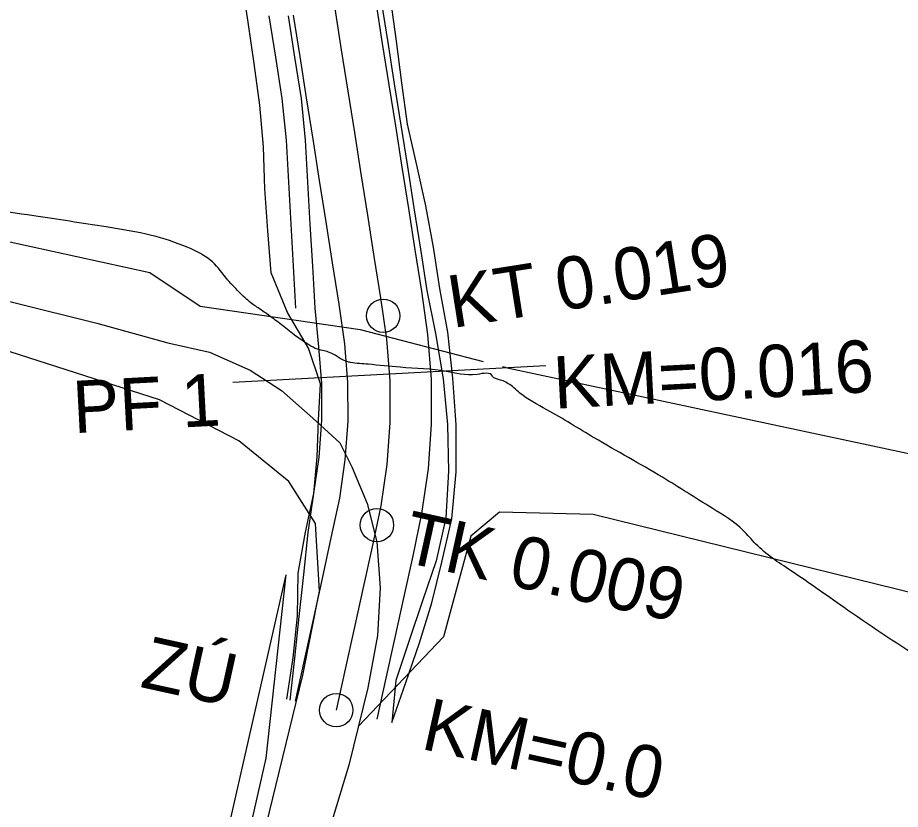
# Model space of a CAD drawing. Extents: x -477701 to -476785, y -1116511 to -1115314.
# Drawn here: x -477025.91 to -476983.69, y -1116139.76 to -1116101.91 of the extents above; entities that cross this region are included whole.
import ezdxf

# ---------------------------------------------------------------- set-up
doc = ezdxf.new("R2010")
doc.units = 0
for name, color, linetype in [('1', 7, 'Continuous'), ('BYBLOCK', 7, 'Continuous'), ('hrana_P', 7, 'Continuous'), ('hrana_R', 7, 'Continuous'), ('POLYGONY_SITUACE_PF', 7, 'Continuous'), ('POLYGONY_SITUACE_PF_POPISY', 7, 'Continuous'), ('POLYGONY_SITUACE_PO', 7, 'Continuous'), ('SVK_STAT', 7, 'Continuous'), ('Vrstevnice_vedlejsi', 7, 'Continuous')]:
    doc.layers.add(name, color=color, linetype=linetype)

msp = doc.modelspace()

# ---------------------------------------------------------------- linework, layer by layer
at = {"layer": 'hrana_P'}
for points in [[(-477014.887, -1116102.126), (-477015.192, -1116100.149)], [(-477007.787, -1116103.031), (-477008.062, -1116101.05)], [(-477014.604, -1116104.106), (-477014.887, -1116102.126)], [(-477007.537, -1116105.017), (-477007.787, -1116103.031)], [(-477014.322, -1116106.086), (-477014.604, -1116104.106)], [(-477007.261, -1116106.998), (-477007.537, -1116105.017)], [(-477014.156, -1116108.085), (-477014.322, -1116106.086)], [(-477006.82, -1116108.953), (-477007.261, -1116106.998)], [(-477014.082, -1116110.098), (-477014.156, -1116108.085)], [(-477006.379, -1116110.908), (-477006.82, -1116108.953)], [(-477013.95, -1116112.102), (-477014.082, -1116110.098)], [(-477006.014, -1116112.875), (-477006.379, -1116110.908)], [(-477013.79, -1116114.101), (-477013.95, -1116112.102)], [(-477005.719, -1116114.854), (-477006.014, -1116112.875)], [(-477013.008, -1116116.003), (-477013.79, -1116114.101)], [(-477005.329, -1116116.942), (-477005.719, -1116114.854)], [(-477011.99, -1116117.708), (-477013.008, -1116116.003)], [(-477005.093, -1116119.151), (-477005.329, -1116116.942)], [(-477011.425, -1116119.408), (-477011.99, -1116117.708)], [(-477011.517, -1116121.159), (-477011.425, -1116119.408)], [(-477004.934, -1116121.38), (-477005.093, -1116119.151)], [(-477011.579, -1116122.908), (-477011.517, -1116121.159)], [(-477004.931, -1116123.627), (-477004.934, -1116121.38)], [(-477011.742, -1116124.658), (-477011.579, -1116122.908)], [(-477005.138, -1116125.872), (-477004.931, -1116123.627)], [(-477012.135, -1116126.503), (-477011.742, -1116124.658)], [(-477005.617, -1116127.937), (-477005.138, -1116125.872)], [(-477012.49, -1116128.473), (-477012.135, -1116126.503)], [(-477006.107, -1116129.877), (-477005.617, -1116127.937)], [(-477012.52, -1116130.514), (-477012.49, -1116128.473)], [(-477006.689, -1116131.797), (-477006.107, -1116129.877)], [(-477012.728, -1116132.516), (-477012.52, -1116130.514)], [(-477007.346, -1116133.7), (-477006.689, -1116131.797)], [(-477013.038, -1116134.495), (-477012.728, -1116132.516)], [(-477008.009, -1116135.602), (-477007.346, -1116133.7)]]:
    msp.add_lwpolyline(points, dxfattribs=at)
at = {"layer": 'hrana_R'}
for points in [[(-477008.452, -1116103.136), (-477008.764, -1116101.161)], [(-477008.517, -1116101.122), (-477008.205, -1116103.097)], [(-477010.739, -1116101.472), (-477010.428, -1116103.448)], [(-477013.568, -1116103.798), (-477013.88, -1116101.823)], [(-477012.65, -1116103.798), (-477012.962, -1116101.823)], [(-477012.403, -1116103.759), (-477012.715, -1116101.784)], [(-477008.141, -1116105.112), (-477008.452, -1116103.136)], [(-477008.205, -1116103.097), (-477007.894, -1116105.073)], [(-477013.257, -1116105.774), (-477013.568, -1116103.798)], [(-477012.339, -1116105.774), (-477012.65, -1116103.798)], [(-477012.092, -1116105.735), (-477012.403, -1116103.759)], [(-477010.428, -1116103.448), (-477010.116, -1116105.423)], [(-477007.829, -1116107.087), (-477008.141, -1116105.112)], [(-477007.894, -1116105.073), (-477007.582, -1116107.049)], [(-477010.116, -1116105.423), (-477009.805, -1116107.399)], [(-477013.057, -1116107.767), (-477013.257, -1116105.774)], [(-477012.139, -1116107.767), (-477012.339, -1116105.774)], [(-477011.781, -1116107.71), (-477012.092, -1116105.735)], [(-477007.518, -1116109.063), (-477007.829, -1116107.087)], [(-477007.582, -1116107.049), (-477007.271, -1116109.024)], [(-477009.805, -1116107.399), (-477009.493, -1116109.375)], [(-477012.943, -1116109.774), (-477013.057, -1116107.767)], [(-477012.025, -1116109.774), (-477012.139, -1116107.767)], [(-477011.469, -1116109.686), (-477011.781, -1116107.71)], [(-477007.206, -1116111.039), (-477007.518, -1116109.063)], [(-477007.271, -1116109.024), (-477006.959, -1116111)], [(-477011.158, -1116111.662), (-477011.469, -1116109.686)], [(-477009.493, -1116109.375), (-477009.182, -1116111.35)], [(-477012.829, -1116111.78), (-477012.943, -1116109.774)], [(-477011.911, -1116111.78), (-477012.025, -1116109.774)], [(-477006.959, -1116111), (-477006.648, -1116112.975)], [(-477009.182, -1116111.35), (-477008.871, -1116113.326)], [(-477006.895, -1116113.014), (-477007.206, -1116111.039)], [(-477012.715, -1116113.787), (-477012.829, -1116111.78)], [(-477011.797, -1116113.787), (-477011.911, -1116111.78)], [(-477010.846, -1116113.637), (-477011.158, -1116111.662)], [(-477006.584, -1116114.99), (-477006.895, -1116113.014)], [(-477006.648, -1116112.975), (-477006.337, -1116114.951)], [(-477008.871, -1116113.326), (-477008.559, -1116115.301)], [(-477012.601, -1116115.794), (-477012.715, -1116113.787)], [(-477011.683, -1116115.794), (-477011.797, -1116113.787)], [(-477010.535, -1116115.613), (-477010.846, -1116113.637)], [(-477006.284, -1116117.052), (-477006.584, -1116114.99)], [(-477006.337, -1116114.951), (-477005.924, -1116117.01)], [(-477010.258, -1116117.509), (-477010.535, -1116115.613)], [(-477008.559, -1116115.301), (-477008.271, -1116117.28)], [(-477012.601, -1116115.794), (-477012.601, -1116115.794)], [(-477011.5, -1116117.652), (-477011.683, -1116115.794)], [(-477008.271, -1116117.28), (-477008.116, -1116119.274)], [(-477006.118, -1116119.193), (-477006.284, -1116117.052)], [(-477005.924, -1116117.01), (-477005.558, -1116119.17)], [(-477011.364, -1116119.405), (-477011.5, -1116117.652)], [(-477010.115, -1116119.355), (-477010.258, -1116117.509)], [(-477011.358, -1116121.164), (-477011.364, -1116119.405)], [(-477010.108, -1116121.206), (-477010.115, -1116119.355)], [(-477008.116, -1116119.274), (-477008.109, -1116121.273)], [(-477006.11, -1116121.341), (-477006.118, -1116119.193)], [(-477005.558, -1116119.17), (-477005.352, -1116121.366)], [(-477011.482, -1116122.919), (-477011.358, -1116121.164)], [(-477010.239, -1116123.053), (-477010.108, -1116121.206)], [(-477008.109, -1116121.273), (-477008.25, -1116123.268)], [(-477006.262, -1116123.483), (-477006.11, -1116121.341)], [(-477005.352, -1116121.366), (-477005.31, -1116123.586)], [(-477011.735, -1116124.659), (-477011.482, -1116122.919)], [(-477010.506, -1116124.885), (-477010.239, -1116123.053)], [(-477008.25, -1116123.268), (-477008.539, -1116125.247)], [(-477006.572, -1116125.608), (-477006.262, -1116123.483)], [(-477005.31, -1116123.586), (-477005.434, -1116125.817)], [(-477012.013, -1116126.53), (-477011.735, -1116124.659)], [(-477010.906, -1116126.773), (-477010.506, -1116124.885)], [(-477008.539, -1116125.247), (-477008.953, -1116127.203)], [(-477006.999, -1116127.633), (-477006.572, -1116125.608)], [(-477005.434, -1116125.817), (-477005.893, -1116127.877)], [(-477012.227, -1116128.53), (-477012.013, -1116126.53)], [(-477011.336, -1116128.727), (-477010.906, -1116126.773)], [(-477008.953, -1116127.203), (-477009.383, -1116129.156)], [(-477007.429, -1116129.586), (-477006.999, -1116127.633)], [(-477005.893, -1116127.877), (-477006.538, -1116129.782)], [(-477012.441, -1116130.531), (-477012.227, -1116128.53)], [(-477011.766, -1116130.68), (-477011.336, -1116128.727)], [(-477009.383, -1116129.156), (-477009.812, -1116131.11)], [(-477007.859, -1116131.54), (-477007.429, -1116129.586)], [(-477006.538, -1116129.782), (-477007.184, -1116131.688)], [(-477012.655, -1116132.532), (-477012.441, -1116130.531)], [(-477012.195, -1116132.633), (-477011.766, -1116130.68)], [(-477009.812, -1116131.11), (-477010.242, -1116133.063)], [(-477008.289, -1116133.493), (-477007.859, -1116131.54)], [(-477007.184, -1116131.688), (-477007.829, -1116133.594)], [(-477012.869, -1116134.533), (-477012.655, -1116132.532)], [(-477012.625, -1116134.586), (-477012.195, -1116132.633)], [(-477010.242, -1116133.063), (-477010.672, -1116135.016)], [(-477008.719, -1116135.446), (-477008.289, -1116133.493)], [(-477007.829, -1116133.594), (-477008.009, -1116135.602)]]:
    msp.add_lwpolyline(points, dxfattribs=at)
at = {"layer": 'POLYGONY_SITUACE_PF'}
msp.add_lwpolyline([(-477015.621, -1116119.334), (-477008.132, -1116118.937), (-477000.642, -1116118.541)], dxfattribs=at)
at = {"layer": 'POLYGONY_SITUACE_PO'}
for centre in [(-477008.423, -1116116.161), (-477008.725, -1116126.169), (-477010.672, -1116135.016)]:
    msp.add_circle(centre, 0.8, dxfattribs=at)
at = {"layer": 'SVK_STAT'}
for p, q in [((-477002.861, -1116125.548), (-477004.234, -1116126.692)), ((-476998.39, -1116125.659), (-477002.861, -1116125.548)), ((-476970.394, -1116132.552), (-476998.39, -1116125.659)), ((-477004.234, -1116126.692), (-477005.543, -1116131.513)), ((-477005.543, -1116131.513), (-477009.615, -1116135.793))]:
    msp.add_line(p, q, dxfattribs=at)
for points in [[(-477082.723, -1116100.585), (-477053.348, -1116106.692), (-477019.581, -1116114.084), (-477017.176, -1116115.701), (-477009.531, -1116116.815), (-477003.649, -1116118.348)], [(-477077.382, -1116101.994), (-477064.814, -1116105.008), (-477053.918, -1116107.659), (-477045.001, -1116110.374), (-477037.67, -1116112.321), (-477030.015, -1116114.548), (-477022.124, -1116116.518), (-477018.731, -1116117.462), (-477016.74, -1116117.894), (-477014.791, -1116118.765), (-477013.283, -1116119.735), (-477011.785, -1116121.05), (-477010.493, -1116122.228), (-477009.932, -1116123.384), (-477009.196, -1116125.14), (-477008.733, -1116126.967), (-477008.566, -1116129.175), (-477008.691, -1116131.452), (-477009.158, -1116133.948), (-477010.072, -1116137.639), (-477012.863, -1116146.838), (-477016.577, -1116158.448)], [(-477018.575, -1116156.174), (-477014.335, -1116141.843), (-477012.264, -1116133.338), (-477011.468, -1116129.334), (-477011.656, -1116126.092), (-477012.943, -1116124.089), (-477015.333, -1116122.135), (-477019.127, -1116120.181), (-477026.711, -1116117.735), (-477038.937, -1116114.281), (-477048.372, -1116111.647), (-477055.317, -1116109.713), (-477065.68, -1116107.165), (-477073.164, -1116105.431)], [(-477002.712, -1116118.592), (-477002.423, -1116118.668), (-476967.162, -1116126.189), (-476939.258, -1116131.196), (-476922.887, -1116134.718)], [(-477013.082, -1116128.546), (-477016.079, -1116141.728), (-477020.409, -1116158.116), (-477023.941, -1116169.95)], [(-477013.082, -1116128.546), (-477014.035, -1116137.316), (-477015.535, -1116143.923), (-477018.303, -1116153.396), (-477020.997, -1116163.011), (-477023.039, -1116169.635)]]:
    msp.add_lwpolyline(points, dxfattribs=at)
at = {"layer": 'Vrstevnice_vedlejsi'}
for points in [[(-476919.326, -1116106.047), (-476920.245, -1116104.554), (-476920.776, -1116103.86), (-476921.381, -1116103.219), (-476922.058, -1116102.629), (-476926.595, -1116098.696), (-476934.992, -1116091.42), (-476947.249, -1116080.799), (-476957.681, -1116072.815), (-476966.287, -1116067.466), (-476973.068, -1116064.753), (-476979.773, -1116062.457), (-476986.401, -1116060.577), (-476992.954, -1116059.115), (-477000.706, -1116057.567), (-477009.657, -1116055.933), (-477019.809, -1116054.213), (-477027.637, -1116052.946), (-477033.142, -1116052.131), (-477036.324, -1116051.768), (-477040.077, -1116051.076), (-477044.402, -1116050.054), (-477049.299, -1116048.702), (-477055.376, -1116047.74), (-477062.632, -1116047.168), (-477071.069, -1116046.985), (-477080.052, -1116047.469), (-477089.579, -1116048.621), (-477099.653, -1116050.441), (-477107.455, -1116051.762), (-477112.986, -1116052.585), (-477116.246, -1116052.91), (-477119.194, -1116053.331), (-477121.829, -1116053.848), (-477124.152, -1116054.461), (-477127.582, -1116055.644), (-477132.118, -1116057.396), (-477137.761, -1116059.718), (-477142.751, -1116062.093), (-477147.089, -1116064.522), (-477150.774, -1116067.004), (-477153.47, -1116068.864), (-477155.178, -1116070.101), (-477155.898, -1116070.715), (-477157.058, -1116072.059), (-477158.657, -1116074.132), (-477160.695, -1116076.934), (-477162.416, -1116079.366), (-477163.821, -1116081.428), (-477164.909, -1116083.119), (-477165.567, -1116084.436), (-477165.796, -1116085.379), (-477165.596, -1116085.947), (-477165.439, -1116086.459), (-477165.323, -1116086.915), (-477165.251, -1116087.314), (-477165.217, -1116087.627), (-477165.222, -1116087.854), (-477165.265, -1116087.995), (-477165.533, -1116088.093), (-477166.028, -1116088.15), (-477166.748, -1116088.165), (-477167.67, -1116088.25), (-477168.793, -1116088.405), (-477170.117, -1116088.631), (-477171.131, -1116088.881), (-477171.834, -1116089.156), (-477172.227, -1116089.454), (-477172.953, -1116089.693), (-477174.011, -1116089.872), (-477175.401, -1116089.992), (-477176.846, -1116090.023), (-477178.345, -1116089.964), (-477179.898, -1116089.816), (-477180.753, -1116089.746)], [(-477172.715, -1116112.801), (-477167.136, -1116109.138), (-477161.306, -1116105.345), (-477157.276, -1116102.766), (-477155.046, -1116101.401), (-477153.814, -1116100.467), (-477153.582, -1116099.964), (-477153.692, -1116099.911), (-477153.923, -1116099.951), (-477154.349, -1116099.892), (-477154.535, -1116099.323), (-477154.142, -1116098.256), (-477153.168, -1116096.691), (-477152.027, -1116095.699), (-477150.718, -1116095.279), (-477149.241, -1116095.431), (-477148.062, -1116095.548), (-477147.179, -1116095.631), (-477146.593, -1116095.679), (-477145.474, -1116095.694), (-477143.82, -1116095.674), (-477141.633, -1116095.621), (-477139.033, -1116095.565), (-477136.018, -1116095.506), (-477132.589, -1116095.444), (-477130.28, -1116095.379), (-477129.089, -1116095.311), (-477129.017, -1116095.24), (-477128.598, -1116095.087), (-477127.831, -1116094.852), (-477126.718, -1116094.536), (-477125.959, -1116094.247), (-477125.553, -1116093.986), (-477125.502, -1116093.751), (-477125.462, -1116093.445), (-477125.433, -1116093.069), (-477125.416, -1116092.623), (-477125.392, -1116092.309), (-477125.362, -1116092.128), (-477125.325, -1116092.079), (-477124.319, -1116091.317), (-477122.343, -1116089.841), (-477119.399, -1116087.652), (-477116.849, -1116086.077), (-477114.693, -1116085.116), (-477112.933, -1116084.77), (-477109.947, -1116084.102), (-477105.735, -1116083.111), (-477100.298, -1116081.799), (-477095.896, -1116080.636), (-477092.529, -1116079.622), (-477090.198, -1116078.757), (-477088.077, -1116077.991), (-477086.167, -1116077.324), (-477084.467, -1116076.756), (-477083.096, -1116076.307), (-477082.056, -1116075.979), (-477081.345, -1116075.772), (-477079.865, -1116075.634), (-477077.616, -1116075.567), (-477074.598, -1116075.569), (-477069.513, -1116075.651), (-477062.361, -1116075.812), (-477053.143, -1116076.053), (-477046.507, -1116076.298), (-477042.452, -1116076.547), (-477040.979, -1116076.8), (-477037.82, -1116077.567), (-477032.974, -1116078.849), (-477026.441, -1116080.646), (-477019.819, -1116082.356), (-477013.108, -1116083.979), (-477006.307, -1116085.514), (-476998.285, -1116088.204), (-476989.042, -1116092.047), (-476978.577, -1116097.043), (-476970.779, -1116100.798), (-476965.647, -1116103.309)], [(-476958.711, -1116147.208), (-476959.078, -1116146.464), (-476960.591, -1116143.949), (-476961.676, -1116142.995), (-476964.164, -1116141.603), (-476968.054, -1116139.773), (-476973.346, -1116137.506), (-476978.137, -1116135.16), (-476982.426, -1116132.734), (-476986.214, -1116130.229), (-476988.94, -1116128.342), (-476990.605, -1116127.073), (-476991.208, -1116126.422), (-476992.697, -1116125.358), (-476995.072, -1116123.883), (-476998.333, -1116121.994), (-477000.603, -1116120.651), (-477001.884, -1116119.853), (-477002.175, -1116119.6), (-477002.446, -1116119.407), (-477002.696, -1116119.274), (-477002.926, -1116119.201), (-477003.085, -1116119.14), (-477003.173, -1116119.09), (-477003.192, -1116119.053), (-477003.938, -1116118.962), (-477005.412, -1116118.82), (-477007.615, -1116118.624), (-477009.14, -1116118.48), (-477009.987, -1116118.389), (-477010.157, -1116118.349), (-477010.337, -1116118.277), (-477010.528, -1116118.174), (-477010.729, -1116118.039), (-477010.969, -1116117.925), (-477011.248, -1116117.832), (-477011.565, -1116117.759), (-477011.989, -1116117.545), (-477012.52, -1116117.189), (-477013.158, -1116116.691), (-477013.732, -1116116.259), (-477014.242, -1116115.893), (-477014.689, -1116115.592), (-477015.231, -1116115.107), (-477015.866, -1116114.438), (-477016.596, -1116113.585), (-477017.807, -1116112.88), (-477019.499, -1116112.323), (-477021.673, -1116111.914), (-477025.137, -1116111.384), (-477029.891, -1116110.731), (-477035.936, -1116109.956), (-477040.994, -1116109.247), (-477045.065, -1116108.604), (-477048.149, -1116108.028), (-477050.24, -1116107.648), (-477051.337, -1116107.463), (-477051.442, -1116107.475), (-477051.76, -1116107.478), (-477052.294, -1116107.471), (-477053.041, -1116107.455), (-477053.829, -1116107.402), (-477054.657, -1116107.312), (-477055.526, -1116107.184), (-477056.225, -1116107.275), (-477056.755, -1116107.586), (-477057.115, -1116108.115), (-477058.258, -1116108.281), (-477060.183, -1116108.084), (-477062.891, -1116107.524), (-477064.739, -1116107.165), (-477065.725, -1116107.008), (-477065.851, -1116107.052), (-477066.81, -1116107.333), (-477068.6, -1116107.851), (-477071.223, -1116108.606), (-477074.182, -1116109.307), (-477077.478, -1116109.952), (-477081.111, -1116110.542), (-477084.154, -1116111.51), (-477086.609, -1116112.855), (-477087.096, -1116113.264), (-477087.538, -1116113.724), (-477087.983, -1116114.18), (-477088.475, -1116114.578), (-477091.848, -1116116.472), (-477096.727, -1116118.537), (-477103.112, -1116120.774), (-477107.858, -1116122.089), (-477110.966, -1116122.482), (-477111.338, -1116122.406), (-477111.701, -1116122.24), (-477112.063, -1116122.063), (-477112.435, -1116121.953), (-477114.04, -1116121.959), (-477115.781, -1116122.501), (-477117.657, -1116123.578), (-477119.532, -1116124.71), (-477121.407, -1116125.898)]]:
    msp.add_spline(points, degree=3, dxfattribs=at)

# ---------------------------------------------------------------- texts
at = {"layer": '1'}
for s, rotation, p in [('KT 0.019', 8.9589, (-477005.112, -1116116.75)), ('TK 0.009', 347.5887, (-477007.589, -1116127.904))]:
    msp.add_text(s, height=2.5, rotation=rotation, dxfattribs=at).set_placement(p)
at = {"layer": 'BYBLOCK'}
msp.add_text('ZÚ          KM=0.0', height=2.5, rotation=347.5887, dxfattribs=at).set_placement((-477020.105, -1116133.898))
at = {"layer": 'POLYGONY_SITUACE_PF_POPISY'}
for s, p in [('KM=0.016', (-477000.226, -1116120.607)), ('PF 1', (-477023.212, -1116121.777))]:
    msp.add_text(s, height=2.5, rotation=3.0324, dxfattribs=at).set_placement(p)

doc.saveas('drawing.dxf')
